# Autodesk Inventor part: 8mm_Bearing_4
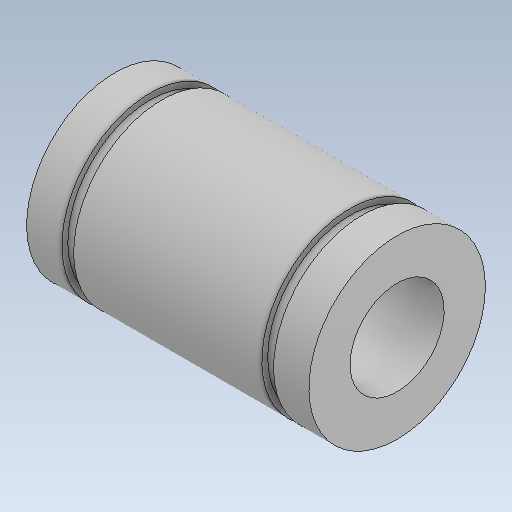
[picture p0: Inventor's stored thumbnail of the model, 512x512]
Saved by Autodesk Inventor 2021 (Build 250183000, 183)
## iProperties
Created: 2026-10
Part Number: 8mm_Bearing_4
Material: Generic
Document SubType Name: Modeling
Designer: hp
Density: 1 g/cm^3
Appearance: Default
Author: hp
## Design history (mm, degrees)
feature "Body1"
body "Solid1"
